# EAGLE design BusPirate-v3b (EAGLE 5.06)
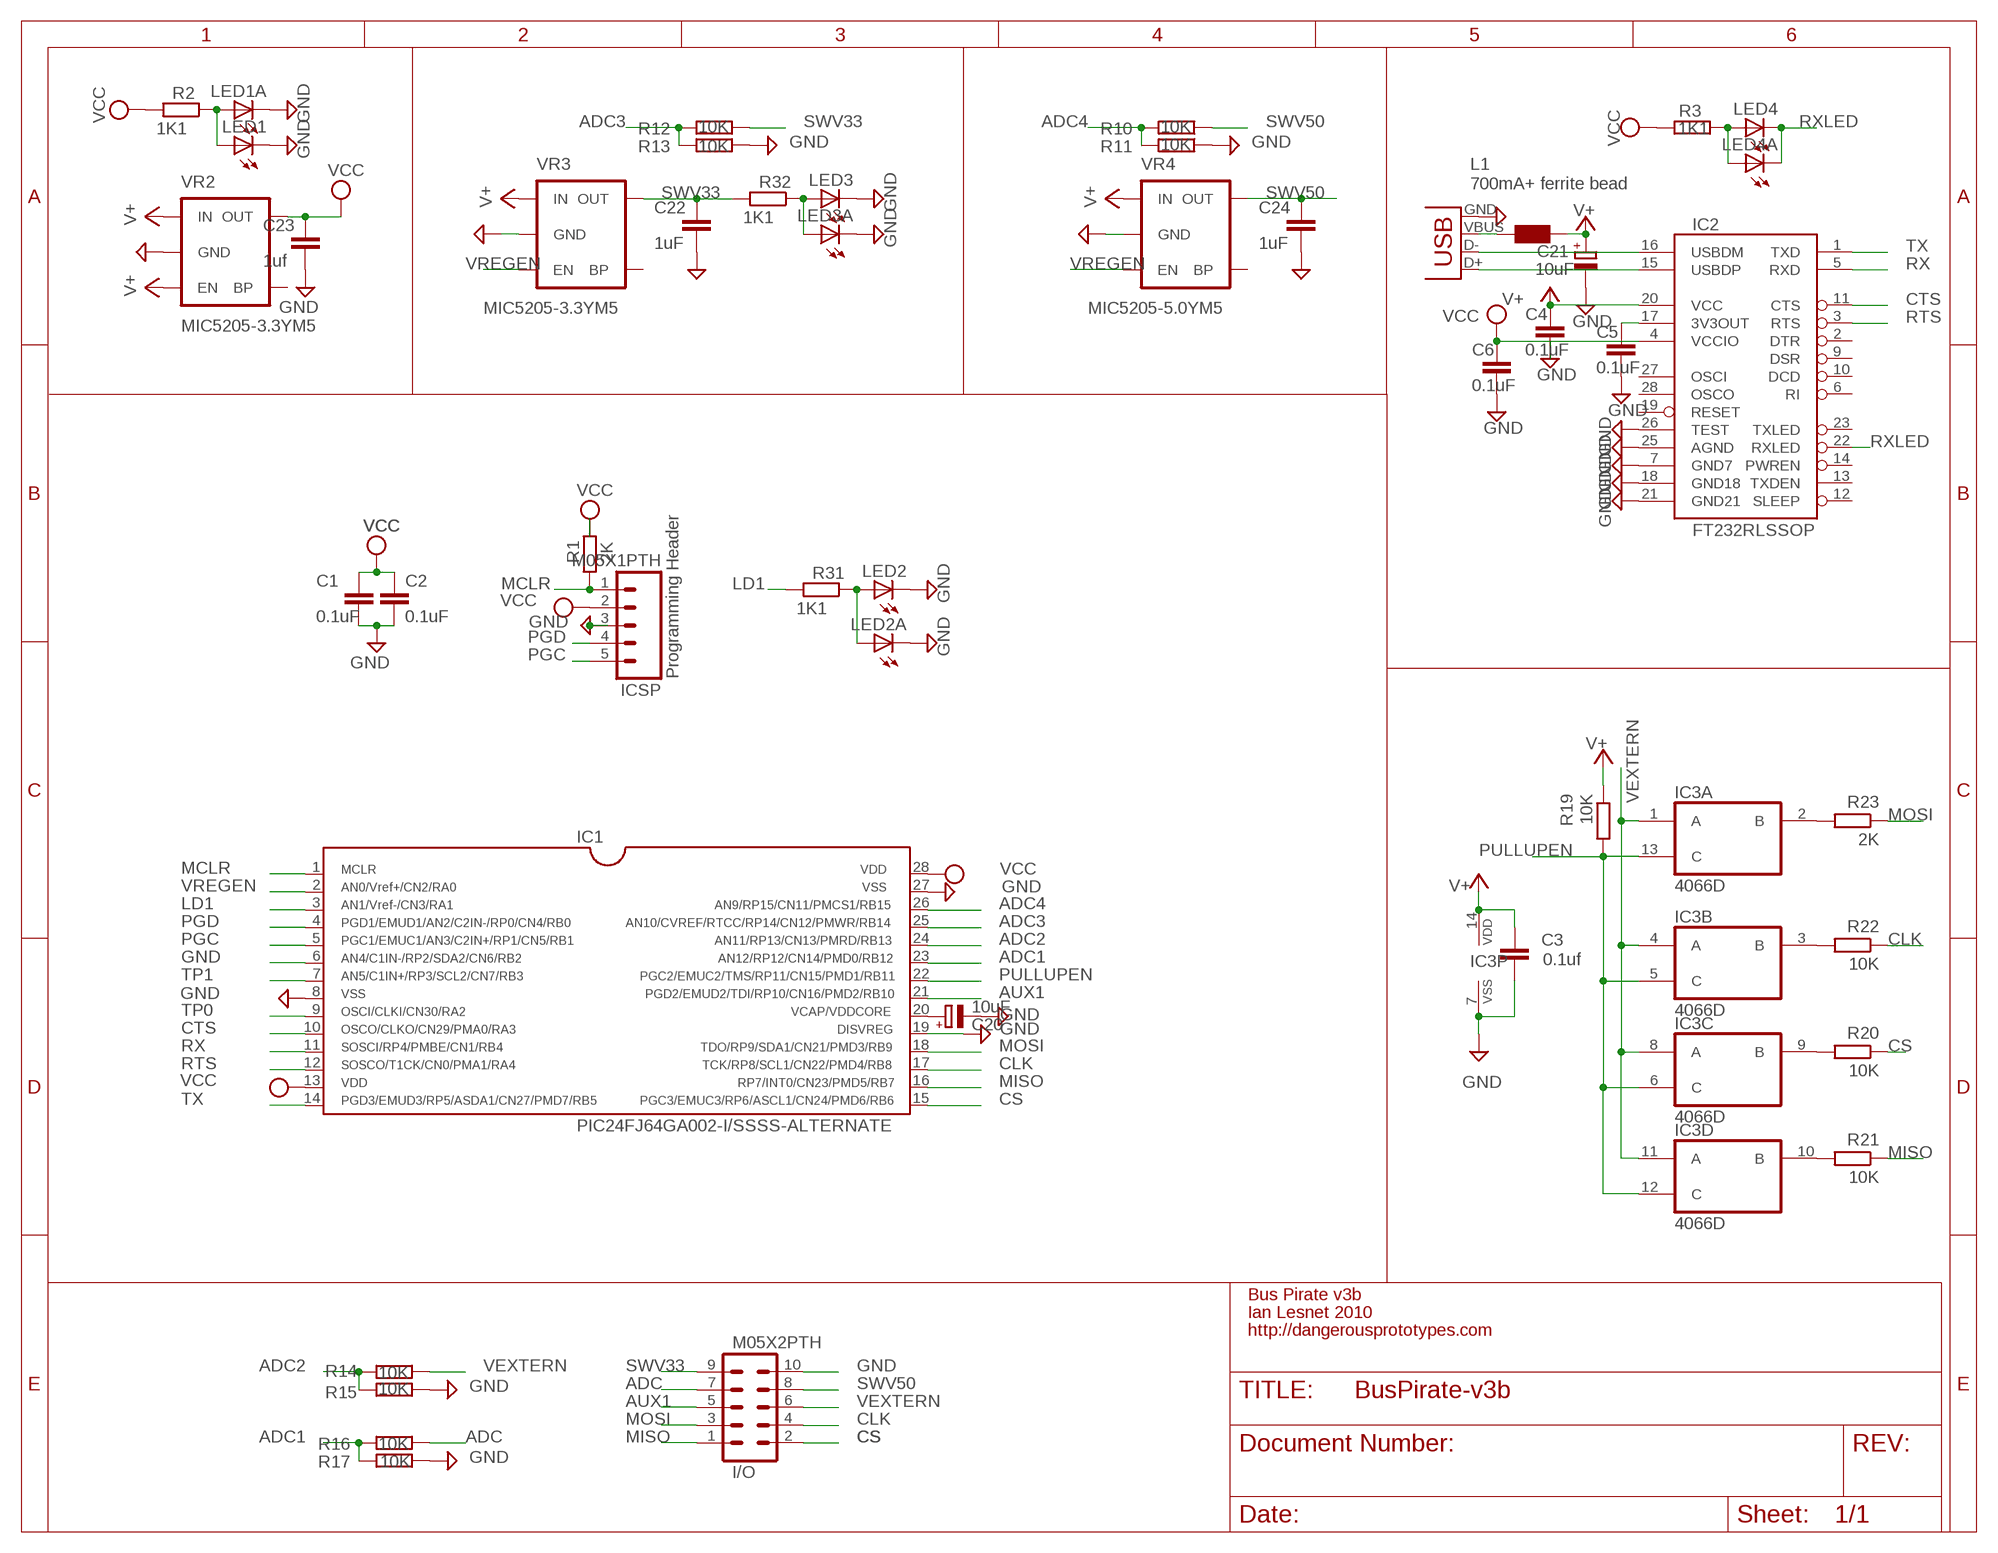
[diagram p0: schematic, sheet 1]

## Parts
C1  0.1uF  C-EUC0805  [C0805]
C2  0.1uF  C-EUC0805  [C0805]
C3  0.1uf  C-EUC0805  [C0805]
C4  0.1uF  C-EUC0805  [C0805]
C5  0.1uF  C-EUC0805  [C0805]
C6  0.1uF  C-EUC0805  [C0805]
C20  10uF  CPOL-EUSMCA  [SMC_A]
C21  10uF  CPOL-EUSMCA  [SMC_A]
C22  1uF  C-EUC0805  [C0805]
C23  1uf  C-EUC0805  [C0805]
C24  1uF  C-EUC0805  [C0805]
I/O  M05X2PTH  [AVR_ICSP]
IC1  PIC24FJ64GA002-I/SSSS-ALTERNATE  [SSOP28DB]
IC2  FT232RLSSOP  [SSOP28DB]
IC3  4066D  [SO14]
ICSP  M05X1PTH  M05  [1X05]
J1  USBSMD  [USB-MINIB]
L1  700mA+ ferrite bead  WE-KIL_0805  [WE-KI_0805_B]
LED1  LEDCHIP-LED0805  [CHIP-LED0805]
LED1A  LEDCHIP-LED0805  [CHIP-LED0805]
LED2  LEDCHIP-LED0805  [CHIP-LED0805]
LED2A  LEDCHIP-LED0805  [CHIP-LED0805]
LED3  LEDCHIP-LED0805  [CHIP-LED0805]
LED3A  LEDCHIP-LED0805  [CHIP-LED0805]
LED4  LEDCHIP-LED0805  [CHIP-LED0805]
LED4A  LEDCHIP-LED0805  [CHIP-LED0805]
R1  2K  R-EU_R0805  [R0805]
R2  1K1  R-EU_M0805  [M0805]
R3  1K1  R-EU_M0805  [M0805]
R10  10K  R-EU_M0805  [M0805]
R11  10K  R-EU_M0805  [M0805]
R12  10K  R-EU_M0805  [M0805]
R13  10K  R-EU_M0805  [M0805]
R14  10K  R-EU_M0805  [M0805]
R15  10K  R-EU_M0805  [M0805]
R16  10K  R-EU_M0805  [M0805]
R17  10K  R-EU_M0805  [M0805]
R19  10K  R-EU_R0805  [R0805]
R20  10K  R-EU_R0805  [R0805]
R21  10K  R-EU_R0805  [R0805]
R22  10K  R-EU_R0805  [R0805]
R23  2K  R-EU_R0805  [R0805]
R31  1K1  R-EU_M0805  [M0805]
R32  1K1  R-EU_M0805  [M0805]
VR2  MIC5205-3.3YM5  V_REG_LDOSMD  [SOT23-5]
VR3  MIC5205-3.3YM5  V_REG_LDOSMD  [SOT23-5]
VR4  MIC5205-5.0YM5  V_REG_LDOSMD  [SOT23-5]

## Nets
$N26: J1.VBUS L1.2
ADC: I/O.7 R16.1
ADC1: IC1.23 R16.2 R17.2
ADC2: IC1.24 R14.2 R15.2
ADC3: IC1.25 R12.2 R13.2
ADC4: IC1.26 R10.2 R11.2
AUX1: I/O.5 IC1.21
CLK: I/O.4 IC1.17 R22.1
CS: I/O.2 IC1.15 R20.1
CTS: IC1.10 IC2.11(CTS)
GND: C1.2 C2.2 C3.2 C4.2 C5.2 C6.2 C20.- C21.- C22.2 C23.2 C24.2 I/O.10 IC1.6 IC1.8 IC1.19 IC1.27 IC2.7(GND7) IC2.18(GND18) IC2.21(GND21) IC2.25(AGND) IC2.26(TEST) IC3.7(P:VSS) ICSP.3 J1.GND LED1.C LED1A.C LED2.C LED2A.C LED3.C LED3A.C R11.1 R13.1 R15.1 R17.1 VR2.2(GND) VR3.2(GND) VR4.2(GND)
LD1: IC1.3 R31.2
MCLR: IC1.1 ICSP.1 R1.1
MISO: I/O.1 IC1.16 R21.1
MOSI: I/O.3 IC1.18 R23.1
N$1: IC3.2(A:B) R23.2
N$2: IC3.3(B:B) R22.2
N$3: C20.+ IC1.20
N$4: IC3.10(D:B) R21.2
N$5: IC3.9(C:B) R20.2
N$6: LED2.A LED2A.A R31.1
N$7: LED1.A LED1A.A R2.1
N$9: C5.1 IC2.17(3V3OUT)
N$13: LED4.A LED4A.A R3.1
N$15: IC2.15(USBDP) J1.D+
N$16: IC2.16(USBDM) J1.D-
N$18: LED3.A LED3A.A R32.1
PGC: IC1.5 ICSP.5
PGD: IC1.4 ICSP.4
PULLUPEN: IC1.22 IC3.5(B:C) IC3.6(C:C) IC3.12(D:C) IC3.13(A:C) R19.2
RTS: IC1.12 IC2.3(RTS)
RX: IC1.11 IC2.5(RXD)
RXLED: IC2.22(RXLED) LED4.C LED4A.C
SWV33: C22.1 I/O.9 R12.1 R32.2 VR3.5(OUT)
SWV50: C24.1 I/O.8 R10.1 VR4.5(OUT)
TP0: IC1.9
TP1: IC1.7
TX: IC1.14 IC2.1(TXD)
V+: C3.1 C4.1 C21.+ IC2.20(VCC) IC3.14(P:VDD) L1.1 R19.1 VR2.1(IN) VR2.3(EN) VR3.1(IN) VR4.1(IN)
VCC: C1.1 C2.1 C6.1 C23.1 IC1.13 IC1.28 IC2.4(VCCIO) ICSP.2 R1.2 R2.2 R3.2 VR2.5(OUT)
VEXTERN: I/O.6 IC3.1(A:A) IC3.4(B:A) IC3.8(C:A) IC3.11(D:A) R14.1
VREGEN: IC1.2 VR3.3(EN) VR4.3(EN)
Unconnected: IC2.2(DTR) IC2.6(RI) IC2.9(DSR) IC2.10(DCD) IC2.12(SLEEP) IC2.13(TXDEN) IC2.14(PWREN) IC2.19(RESET) IC2.23(TXLED) IC2.27(OSCI) IC2.28(OSCO) VR2.4(BP) VR3.4(BP) VR4.4(BP)

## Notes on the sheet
- Programming Header
- Bus Pirate v3b
- Ian Lesnet 2010
- http://dangerousprototypes.com

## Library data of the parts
C1-C6 C22-C24 = rcl:C-EU: CAPACITOR, European symbol
C20 C21 = rcl:CPOL-EU: POLARIZED CAPACITOR, European symbol
I/O = SparkFun:M05X2: Header 5x2 Standard 10-pin dual row 0.1" header. Commonly used with AVR-ISP. Use with Spark Fun Electronics SKU: PRT-00778
IC1 = microchip-pic24:PIC24FJ64GA002-I/SS
IC2 = SparkFun:FT232RL: USB UART FT232RL 4th Generation USB UART (USB <-> Serial) Controller. Spark Fun Electronics SKU : COM-00650
IC3 = 40xx:4066: Quad bilateral ANALOG SWITCH
ICSP = SparkFun:M05: Header 5 Standard 5-pin 0.1" header. Use with straight break away headers (SKU : PRT-00116), right angle break away headers (PRT-00553), swiss pins (PRT-00743), machine pins (PRT-00117), and female headers (PRT-00115). Molex polarized connector foot print use with SKU : PRT-08230 with associated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
J1 = SparkFun:USB: USB Connectors USB-B-PTH is fully proven SKU : PRT-00139 USB-miniB is fully proven SKU : PRT-00587 USB-A-PCB is untested. USB-A-H is throughly reviewed, but untested. Spark Fun Electronics SKU : PRT-00437 USB-B-SMT is throughly reviewed, but untested. Needs silkscreen touching up. USB-A-S has not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
L1 = wuerth-elektronik:WE-KIL: SMD Wire Wound Ceramic Inductor WE-KIL
LED1 LED1A LED2 LED2A LED3 LED3A LED4 LED4A = led:LED: LED
R1 R2 R19-R23 R31 R32 = rcl:R-EU_: RESISTOR, European symbol
R3 R10-R17 = resistor:R-EU_: RESISTOR, European symbol
VR2-VR4 = SparkFun:V_REG_LDO: Voltage Regulator LDO Standard 150mA LDO voltage regulator in SOT-23 layout. Micrel part MIC5205. BP (by-pass) pin is used to lower output noise with 470pF cap.

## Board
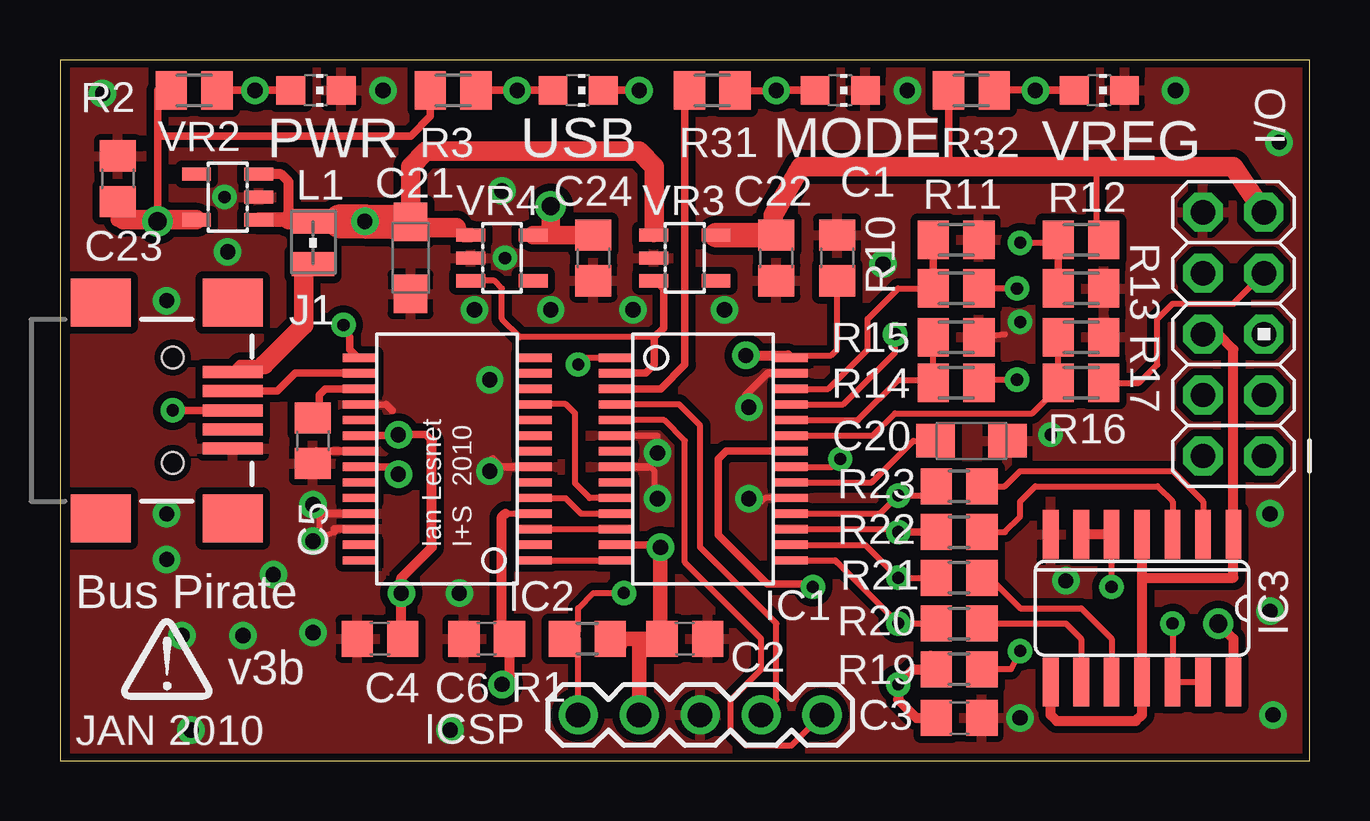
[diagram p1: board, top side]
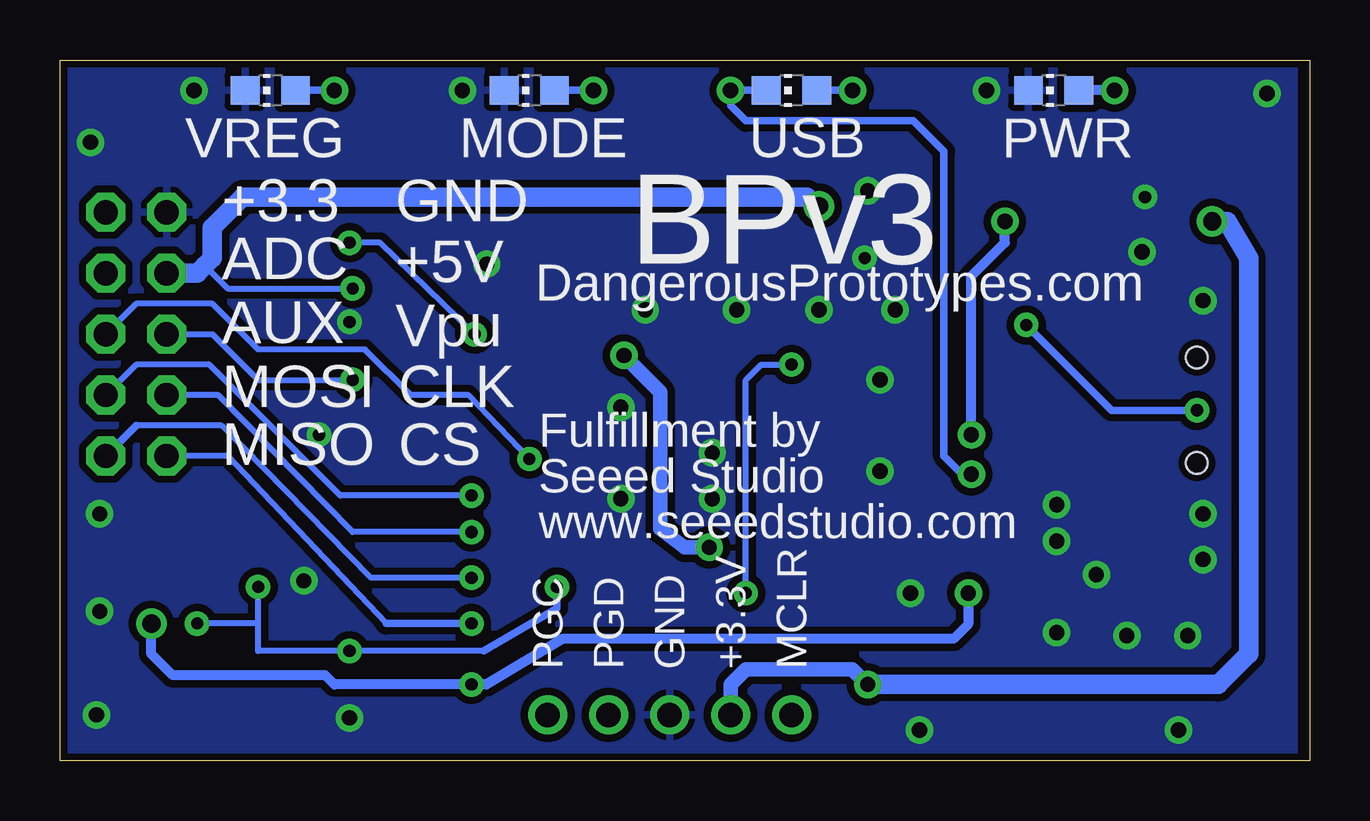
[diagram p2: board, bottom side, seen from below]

Size 52.07 x 29.21 mm. Coordinates in mm from the lower left corner, seen from the top.
Outline: 0,29.21 0,0 52.07,0 52.07,29.21 0,29.21
Copper layers (1*16): Top 0.035mm / dielectric 1.5mm / Bottom 0.035mm
Design rules "SparkFun": minimum track width 8mil, minimum drill 20mil, track to track 8mil, track to pad 8mil, pad to pad 8mil, via to via 8mil, smd to smd 8mil, copper to edge 10mil, drill to drill 8mil, minimum pad ring 12mil, minimum via ring 10mil, stop-mask expansion 4mil, vias tented up to drill 25mil, thermal gap 10mil
tRestrict: area 12.1,9.9 to 13,10

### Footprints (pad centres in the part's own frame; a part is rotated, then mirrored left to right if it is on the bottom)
C0805 = smd 1.3 x 1.5: 1 -0.95,0; 2 0.95,0
SMC_A = smd 1.6 x 1.4: + -1.5,0; - 1.5,0
AVR_ICSP = drill 1.016 octagon: 1 -1.27,5.08; 2 1.27,5.08; 3 -1.27,2.54; 4 1.27,2.54; 5 -1.27,0; 6 1.27,0; 7 -1.27,-2.54; 8 1.27,-2.54; 9 -1.27,-5.08; 10 1.27,-5.08
SSOP28DB = smd 0.348 x 1.397: 1 -4.225,-3.656; 2 -3.575,-3.656; 3 -2.925,-3.656; 4 -2.275,-3.656; 5 -1.625,-3.656; 6 -0.975,-3.656; 7 -0.325,-3.656; 8 0.325,-3.656; 9 0.975,-3.656; 10 1.625,-3.656; 11 2.275,-3.656; 12 2.925,-3.656; 13 3.575,-3.656; 14 4.225,-3.656; 15 4.225,3.656; 16 3.575,3.656; 17 2.925,3.656; 18 2.275,3.656; 19 1.625,3.656; 20 0.975,3.656; 21 0.325,3.656; 22 -0.325,3.656; 23 -0.975,3.656; 24 -1.625,3.656; 25 -2.275,3.656; 26 -2.925,3.656; 27 -3.575,3.656; 28 -4.225,3.656
SO14 = smd 0.66 x 2.032: 1 -3.81,-3.073; 2 -2.54,-3.073; 3 -1.27,-3.073; 4 0,-3.073; 5 1.27,-3.073; 6 2.54,-3.073; 7 3.81,-3.073; 8 3.81,3.073; 9 2.54,3.073; 10 1.27,3.073; 11 0,3.073; 12 -1.27,3.073; 13 -2.54,3.073; 14 -3.81,3.073
1X05 = drill 1.016 round: 1 0,0; 2 2.54,0; 3 5.08,0; 4 7.62,0; 5 10.16,0
USB-MINIB = smd 2.5 x 0.5: D+ 2.5,0; D- 2.5,0.8; GND 2.5,-1.6; ID 2.5,-0.8; VBUS 2.5,1.6 | smd 2.5 x 2: GND@1 -3,-4.5; GND@2 -3,4.5; GND@3 2.5,4.5; GND@4 2.5,-4.5 | hole 0.9: 0,2.2; 0,-2.2
WE-KI_0805_B = smd 1.02 x 1.78: 1 -0.89,0; 2 0.89,0
CHIP-LED0805 = smd 1.2 x 1.2: A 0,-1.05; C 0,1.05
R0805 = smd 1.3 x 1.5: 1 -0.95,0; 2 0.95,0
M0805 = smd 1.3 x 1.6: 1 -0.95,0; 2 0.95,0
SOT23-5 = smd 0.55 x 1.2: 1 -0.95,-1.3; 2 0,-1.3; 3 0.95,-1.3; 4 0.95,1.3; 5 -0.95,1.3

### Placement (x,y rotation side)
C1  32.38,20.95 90 top
C2  26.04,5.08 0 top
C3  37.46,1.78 0 top
C4  13.33,5.08 180 top
C5  10.54,13.34 270 top
C6  17.78,5.08 180 top
C20  37.97,13.34 0 top
C21  14.61,20.95 270 top
C22  29.85,20.95 270 top
C23  2.41,24.26 90 top
C24  22.23,20.95 270 top
I/O  48.89,17.78 180 top
IC1  26.8,12.57 270 top
IC2  16.13,12.57 90 top
IC3  45.09,6.35 180 top
ICSP  21.59,1.91 0 top
J1  4.7,14.61 0 top
L1  10.54,21.59 270 top
LED1  10.67,27.94 270 top
LED1A  10.67,27.94 90 bottom
LED2  32.51,27.94 270 top
LED2A  32.51,27.94 90 bottom
LED3  43.31,27.94 270 top
LED3A  43.31,27.94 90 bottom
LED4  21.59,27.94 270 top
LED4A  21.59,27.94 90 bottom
R1  21.97,5.08 0 top
R2  5.59,27.94 180 top
R3  16.38,27.94 180 top
R10  37.34,19.69 180 top
R11  37.34,21.72 180 top
R12  42.54,21.72 180 top
R13  42.54,19.69 180 top
R14  37.34,15.75 180 top
R15  37.34,17.65 180 top
R16  42.54,15.75 180 top
R17  42.54,17.65 180 top
R19  37.46,3.81 0 top
R20  37.46,5.71 0 top
R21  37.46,7.62 0 top
R22  37.46,9.52 0 top
R23  37.46,11.43 0 top
R31  27.18,27.94 180 top
R32  37.97,27.94 180 top
U$1  [DP-LOGO]  2.54,2.54 0 top
VR2  6.98,23.49 90 top
VR3  26.04,20.95 270 top
VR4  18.42,20.95 270 top

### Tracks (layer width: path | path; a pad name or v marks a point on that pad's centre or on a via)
$N26
  Top 0.406: 8.51,16.51 7.5,16.51 J1.VBUS
  Top 0.813: L1.2 10.16,20.45 10.16,18.16 8.51,16.51
ADC
  Top 0.254: I/O.7 48.89,19.05 46.35,19.05 45.72,18.41 45.72,16.51 44.96,15.75 R16.1
ADC1
  Top 0.254: R17.2 R16.2 41.59,15.24 41.27,15.24 40.51,14.48 34.8,14.48 33.87,13.55 IC1.23
ADC2
  Top 0.254: R15.2 R14.2 36.39,15.88 34.92,15.88 33.25,14.2 IC1.24
ADC3  (via drill 0.51)
  Top 0.254: v34.8,17.78 34.8,17.02 32.63,14.85 IC1.25 | v40,21.59 41.47,21.59 R12.2
  Top 0.305: R13.2 R12.2 41.59,21.91
  Bottom 0.254: v40,21.59 38.73,21.59 v34.8,17.78
ADC4
  Top 0.254: IC1.26 32.01,15.5 33.66,17.15 33.66,18.41 34.92,19.69 R10.2
  Top 0.305: R10.2 R11.2
  Top 0.406: R10.2 36.2,19.69
AUX1  (via drill 0.51)
  Top 0.254: IC1.21 32.19,12.25 v32.51,12.57
  Bottom 0.254: I/O.5 48.89,19.05 45.72,19.05 43.81,17.15 39.37,17.15 37.46,15.24 35.05,15.24 v32.51,12.57
CLK  (via drill 0.51)
  Top 0.254: IC1.17 34.8,9.65 v34.92,9.52
  Top 0.305: v34.92,9.52 R22.1
  Bottom 0.254: I/O.4 45.47,15.24 39.88,9.52 v34.92,9.52
CS  (via drill 0.51)
  Top 0.254: R20.1 v34.92,5.71 32.38,8.25 | 32.38,8.25 32.35,8.29 | IC1.15 32.29,8.35 32.38,8.25
  Bottom 0.254: I/O.2 45.09,12.7 38.48,5.71
  Bottom 0.305: v34.92,5.71 38.48,5.71
CTS
  Top 0.254: IC1.10 22.07,10.95 21.46,11.56 21.46,14.48 21.08,14.86 19.8,14.86 IC2.11
GND  (via drill 0.51, 0.64)
  Top 0.254: IC2.18 13.6,14.85 | R15.1 39.37,17.78 | 24.58,12.25 24.77,12.07 24.77,11.05 v24.89,10.92 | IC1.19 29.36,10.95 29.21,10.8 | 10.79,10.16 10.79,9.52 | v10.54,9.14 11.43,9.52 | IC1.6 24.89,13.55 v24.89,12.83
  Top 0.305: IC2.7 18.36,12.25 18.03,12.57 | 13.6,14.85 13.84,14.61 | IC1.27 29.48,16.15 28.58,15.24 28.58,14.86 v28.7,14.73 | IC1.8 24.58,12.25 | IC2.21 10.66,12.9 C5.2 | IC2.25 10.93,10.3 10.79,10.16 | IC2.26 11.43,9.65 11.43,9.52
  other vias: 41.91,7.49 50.42,6.22 50.55,1.91 41.27,13.59 40,18.29 34.29,20.7 4.45,10.29 4.45,19.18 35.31,27.94 28.7,10.92 40,1.78 50.42,10.29 50.8,25.78 23.88,18.8 20.45,18.8 18.42,23.75 17.27,18.8 17.91,15.88 5.08,5.21 4.45,8.38 10.54,10.67 13.46,27.94 27.69,18.8 18.54,20.95 5.46,1.27 46.48,27.94 8.89,7.75 17.91,12.07 7.62,5.21 1.78,27.81 16.64,6.98 10.54,5.33 16.26,1.27 6.86,23.49 6.98,21.21
  pour Top (isolate 0.305): 0.64,29.21 52.07,29.21 52.07,0 0.64,0
  pour Bottom (isolate 0.305): 0.64,29.21 52.07,29.21 52.07,0 0.64,0
LD1
  Top 0.305: IC1.3 25.02,15.5 26.04,16.51 26.04,27.62
  Top 0.406: 26.04,27.62 R31.2
MCLR  (via drill 0.51)
  Top 0.254: IC1.1 21.88,16.8 v21.59,16.51 | v23.5,6.98 22.23,6.98 21.59,6.35 21.59,5.39 R1.1 21.59,5.08 ICSP.1
  Bottom 0.254: v21.59,16.51 22.86,16.51 23.5,15.88 v23.5,6.98
MISO  (via drill 0.51)
  Top 0.254: v34.92,7.62 R21.1 | v34.92,7.62 34.82,7.73 | IC1.16 33.55,9 v34.92,7.62
  Bottom 0.254: 48.89,13.97 45.34,13.97 39.12,7.62 v34.92,7.62
  Bottom 0.305: 48.89,13.97 I/O.1
MOSI  (via drill 0.51)
  Top 0.254: IC1.18 34.17,10.3 v34.92,11.05 36.13,11.05 R23.1
  Bottom 0.254: I/O.3 48.89,16.51 45.85,16.51 40.39,11.05 v34.92,11.05
N$1
  Top 0.254: IC3.2 47.62,10.8 46.35,12.07 40,12.07 39.37,11.43 R23.2
N$2
  Top 0.254: R22.2 39.37,9.52 40,10.16 40,10.8 40.64,11.43 45.72,11.43 46.35,10.8 IC3.3
N$3
  Top 0.254: IC1.20 33.82,11.6 35.56,13.34 C20.+
N$4
  Top 0.254: R21.2 38.73,7.62 40,6.35 42.54,6.35 43.81,5.08 IC3.10
N$5
  Top 0.254: R20.2 41.91,5.71 42.54,5.08 IC3.9
N$6  (via drill 0.64)
  Top 0.305: 28.29,27.91 LED2A.A v29.85,27.94
  Top 0.406: R31.1 28.29,27.91
  Bottom 0.305: v29.85,27.94 LED2A.A
N$7  (via drill 0.64)
  Top 0.305: LED1A.A v8.13,27.94 R2.1
  Top 0.406: R2.1 6.35,27.94
  Bottom 0.406: v8.13,27.94 LED1A.A
N$9
  Top 0.305: IC2.17 11.05,15.5 10.79,15.24 10.79,14.54 C5.1
N$13  (via drill 0.64)
  Top 0.305: R3.1 v19.05,27.94 | v19.05,27.94 LED4A.A v19.05,27.94
  Bottom 0.305: v19.05,27.94 LED4A.A
N$15  (via drill 0.51)
  Top 0.305: v4.7,14.61 J1.D+ | IC2.15 12.41,16.8 12.06,17.15 12.06,17.65 v11.81,18.16
  Bottom 0.305: v4.7,14.61 8.26,14.61 v11.81,18.16
N$16
  Top 0.254: IC2.16 12.49,16.13
  Top 0.305: J1.D- 9.05,15.41 9.8,16.15 IC2.16
N$18  (via drill 0.64)
  Top 0.305: R32.1 42.23,27.97 | LED3A.A v40.64,27.94
  Top 0.406: 42.23,27.97 LED3A.A
  Bottom 0.305: v40.64,27.94 LED3A.A
PGC
  Top 0.254: IC1.5 25.17,14.2 26.04,13.34 26.04,8.25 29.21,5.08 29.21,3.81 27.94,2.54 27.94,1.27 28.58,0.64 30.48,0.64 ICSP.5
PGD
  Top 0.254: IC1.4 25.79,14.85 26.67,13.97 26.67,8.89 29.85,5.71 29.85,2.54 ICSP.4
PULLUPEN  (via drill 0.51)
  Top 0.254: v46.35,5.71 IC3.12 IC3.13 | v43.81,7.24 IC3.5 | R19.2 39.62,3.81 v40,4.57
  Top 0.305: IC1.22 27.76,12.9 27.43,12.57 27.43,9.4 29.46,7.37 31.24,7.37 v31.37,7.24
  Top 0.406: IC3.5 IC3.6
  Bottom 0.254: 43.81,5.71 43.81,4.57 v40,4.57 34.42,4.57 | 43.81,5.71 v43.81,7.24 | 43.81,5.71 v46.35,5.71
  Bottom 0.305: v31.37,7.24 31.37,6.35 34.42,4.57
RTS
  Top 0.254: IC2.3 IC1.12
RX
  Top 0.254: IC1.11 21.71,10.3 21.06,10.95 IC2.5
RXLED  (via drill 0.64)
  Top 0.305: v24.13,27.94 LED4A.C | IC2.22 14.03,12.25 v14.1,11.94
  Top 0.406: LED4A.C 22.23,27.94
  Bottom 0.305: LED4A.C v24.13,27.94 24.13,27.3 23.5,26.67 16.51,26.67 15.24,25.4 15.24,12.7 14.48,11.94 v14.1,11.94
SWV33
  Top 0.254: R12.1 43.18,21.59 43.18,24.77
  Top 0.305: 37.02,24.83 R32.2
  Top 0.406: R32.2 37.15,27.94 | 36.83,24.77 37.02,24.83
  Top 0.61: 29.72,21.91 C22.1 29.17,21.91
  Top 0.813: I/O.9 48.89,24.77 43.18,24.77 36.83,24.77 30.86,24.77 29.72,22.73 29.72,21.91
  Top 1.016: VR3.5 29.17,21.91
SWV50  (via drill 0.51, 0.76)
  Top 0.254: v39.88,19.69 R10.1
  Top 0.61: 20.32,21.91 20.45,22.03 | 21.68,21.91 C24.1
  Top 0.762: VR4.5 20.32,21.91 21.68,21.91 | 20.45,22.03 v20.45,23.11
  Bottom 0.254: v39.88,19.69 45.09,19.69 46.04,20.64
  Bottom 0.61: 20.7,23.24 20.96,23.49
  Bottom 0.813: I/O.8 46.35,20.32 46.04,20.64 45.72,20.95 45.72,22.23 44.45,23.49 20.96,23.49 | v20.45,23.11 20.7,23.24
TX
  Top 0.254: IC2.1 IC1.14
V+  (via drill 0.51, 0.64, 0.76)
  Top 0.254: IC3.14 48.89,2.86 | 36.26,4.38 R19.1 36.52,3.49
  Top 0.305: IC2.20 14.06,13.55 v14.1,13.59 15.24,13.59 15.49,13.34
  Top 0.406: C4.1 14.22,5.78 14.22,7.62 | 36.26,4.38 36.26,3.88 36.2,3.81 35.56,3.81 v34.92,3.18 34.92,2.54 35.69,1.78 C3.1 | 14.22,7.62 v14.22,6.98 | 14.22,7.62 15.49,8.89 15.49,13.34 | IC3.14 48.89,5.08 v48.26,5.71 | 9.53,22.55 9.53,24.13 9.21,24.45 VR2.3 8.26,24.48
  Top 0.61: 9.53,22.55 VR2.1 | VR4.1 16.83,21.91 16.51,22.23 | VR3.1 24.74,22.2 24.77,22.23
  Top 0.813: 14.61,22.48 14.61,24.77 15.24,25.4 24.13,25.4 24.77,24.77 24.77,22.23 | 16.51,22.23 14.83,22.23 C21.+ | 9.53,22.55 10.48,22.55 L1.1
  Top 1.016: 14.61,22.48 C21.+ | v12.7,22.48 | L1.1 11.68,22.48
  Top 1.422: 14.61,22.48 v12.7,22.48 11.68,22.48
  Bottom 0.406: v48.26,5.71 48.26,4.45 47.37,3.56 41.02,3.56 40.64,3.18 v34.92,3.18 34.29,3.18 31.12,5.08 14.83,5.08 14.23,5.68 v14.23,6.98 v14.22,6.98 | v14.1,13.59 14.1,20.19 12.7,21.59 v12.7,22.48
VCC  (via drill 0.64, 0.76)
  Top 0.254: R1.2 23.5,4.76 | 30.33,16.89 32.13,16.89 32.38,17.15 C1.1 | 18.55,10.3 IC2.4 | C6.1 18.42,5.39
  Top 0.305: IC1.13 24.91,9 v25.02,8.89 | 30.33,16.89 30.36,16.89 IC1.28 | R2.2 4.06,27.94 4.06,26.03 | v4.06,22.48 4.06,26.03 | R3.2 15.43,26.86 14.61,26.03 4.06,26.03
  Top 0.406: 25.4,5.39 C2.1 25.02,5.4 | v25.02,8.89 24.66,9 | v28.58,16.89 30.33,16.89 | 18.55,10.3 18.42,10.16 18.42,5.39 | C6.1 18.73,3.49 v18.42,3.18 | R3.2 15.49,27.81
  Top 0.61: 24.13,5.08 R1.2 | 24.13,5.08 C2.1 | 25.02,5.4 v25.02,8.89 | ICSP.2 24.13,5.08 | 2.62,22.55 2.41,22.55 C23.1
  Top 0.813: 2.62,22.55 VR2.5 4.38,22.55 v4.06,22.48
  Bottom 0.61: ICSP.2 24.13,3.18 23.5,3.81 19.05,3.81 v18.42,3.18 | v25.02,8.89 26.04,8.89 27.05,9.65 27.05,15.37 v28.58,16.89
  Bottom 0.813: v4.06,22.48 3.43,22.48 2.54,20.95 2.54,4.45 3.81,3.18 v18.42,3.18
VEXTERN  (via drill 0.51)
  Top 0.254: v39.88,15.88 38.41,15.88 R14.1
  Top 0.406: 45.09,7.62 48.89,7.62 IC3.1 48.89,17.15 48.26,17.78 I/O.6 | IC3.8 41.27,1.91 41.53,1.65 44.83,1.65 45.09,1.91 IC3.11 45.09,7.62 | 45.09,7.62 IC3.4
  Bottom 0.254: I/O.6 45.72,17.78 43.81,15.88 v39.88,15.88
VREGEN
  Top 0.254: VR4.3 18.1,20.01 18.42,19.69 18.42,18.41 19.18,17.65 24.77,17.65
  Top 0.305: VR3.3 24.77,19.98 24.86,19.98 25.15,19.69 25.15,18.03 24.77,17.65 24.77,16.51 24.4,16.15 IC1.2

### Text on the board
tNames: PWR | USB | MODE | VREG | 2010 | Ian Lesnet | I+S | Bus Pirate | v3b | JAN 2010
bNames: PWR | USB | MODE | VREG | GND | +3.3 | BPv3 | +5V | ADC | DangerousPrototypes.com | Vpu | AUX | CLK | MOSI | Fulfillment by | CS | MISO | Seeed Studio | www.seeedstudio.com | MCLR | +3.3V | GND | PGD | PGC
Reference: GND | +3v | +5v | ADC | Vpu | AUX1 | CLK | MOSI | USB | CS | MISO | I/O header | MCLR | +3.3V | GND | DATA | CLOCK | Bus Pirate v3b | Ian Lesnet | Programming Header | CC-0 | April 2010 | http://dangerousprototypes.com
